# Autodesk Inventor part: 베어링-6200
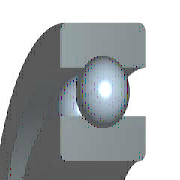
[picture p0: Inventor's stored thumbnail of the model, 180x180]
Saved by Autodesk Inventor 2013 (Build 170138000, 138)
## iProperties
Created: 2012-02
Part Number: 베어링-6200
Material: 강철, 연강
Description: 깊은 그루브 볼 베어링
Document SubType Name: Modeling
Standard: KS B 2023
Designer: mduedu
Standards Organization: KS
Language: ko-KR
Size Designation: 6200 - 10 x 30 x 9
Categories: <MemberInstance><Categories><Category DisplayName="샤프트 부품" InternalName="7f7aeb1f-a693-4053-b835-cee3144e0d98" Mnemonic="SHFT"><Category DisplayName="베어링" Inter
Density: 1 g/cm^3
IsCustomPart: 1
Author: mduedu
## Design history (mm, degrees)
sketch "스케치" dims "d0" = 5.2 (= -0.26 x WD + 0.26 x BD)
  geometry: L1 (1.9, 10)-(7.1, 10); L2 (4.5, 10)-(4.5, 7.4); L3 (4.5, 10)-(4.5, 12.6); L4 (2.568, 8.26)-(0, 8.26); L5 (0, 5)-(9, 5); L6 (2.568, 11.74)-(0, 11.74); L7 (0, 15)-(9, 15); L8 (9, 5)-(9, 8.26); L9 (6.432, 8.26)-(9, 8.26); L10 (6.432, 11.74)-(9, 11.74); L11 (9, 15)-(9, 11.74); L12 (-1.4, 0)-(8.4, 0) reference; L13 (0, -0.3)-(0, 5.3) reference
  constraints: 22 end point, 4 point on line, 2 collinear, 2 perpendicular, 2 symmetric about line, 1 midpoint, 1 parallel, 14 other
  dimensions: "d9" = 10 diameter of L5 L12 (= WD); "d11" = 30 diameter of L7 L12 (= BD); "d12" = 9 distance between parallel lines of L8 L13 (= KB); "d13" = 16.52 diameter of L9 L12 (= 0.326 x BD + 0.674 x WD)
revolve "본체" stored, may be unused: angle "d6" = 90 deg
revolve "볼" stored, may be unused: angle "d7" = 90 deg
pattern_circular "IDS_ARRAYBALL[SIMPL:T]" dims angle "d3" = 360 deg
body "Solid1"
fillet "모깎기1" dims "d1" = 0.6 (= KRS)
other parameters: "WD" = 10 [user parameter; used in 5 equation terms], "BD" = 30 [user parameter; used in 5 equation terms], "KB" = 9 [user parameter; used in 1 equation term], "KRS" = 0.6 [user parameter; used in 1 equation term], "d4" = 0, "d5" = 0, "d8" = 0, "d14" = 0, "d15" = 0, "BBA" = 0 [user parameter], "BC0" = 2360000 [user parameter], "BC" = 5070000 [user parameter], "BR" = 15 (= 0.5 x BD) [user parameter], "WR" = 5 (= 0.5 x WD) [user parameter]
